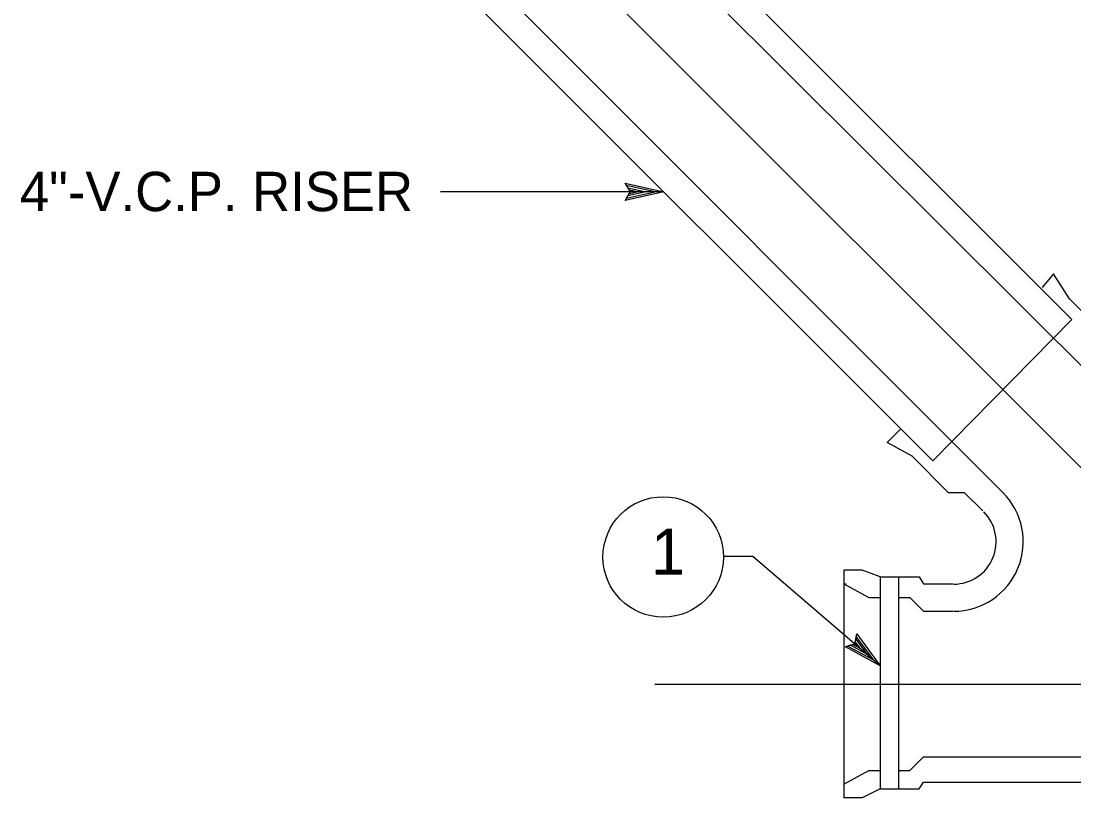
# Model space of a CAD drawing. Extents: x -119017 to -116080, y -104449 to -102845.
# Drawn here: x -116559.2 to -116398.8, y -103492.8 to -103374.5 of the extents above; entities that cross this region are included whole.
import ezdxf

# ---------------------------------------------------------------- set-up
doc = ezdxf.new("R2010")
doc.units = 0
for name, color, linetype in [('G-MARK', 7, 'Continuous'), ('G-TEXT', 7, 'Continuous'), ('Misc CnstDet(22)', 7, 'Continuous')]:
    doc.layers.add(name, color=color, linetype=linetype)

msp = doc.modelspace()

# ---------------------------------------------------------------- linework, layer by layer
at = {"layer": 'G-MARK'}
msp.add_line((-116461.26, -103400.51), (-116495.28, -103400.51), dxfattribs=at)
msp.add_lwpolyline([(-116428.29, -103472.7), (-116447.73, -103456.04), (-116452.24, -103456.04)], dxfattribs=at)
msp.add_circle((-116461.36, -103456.12), 9.18, dxfattribs=at)
at = {"layer": 'G-TEXT'}
for points in [[(-116467.17, -103399.19), (-116461.26, -103400.51), (-116467.17, -103401.82), (-116466.96, -103401.47), (-116462.63, -103400.51), (-116466.96, -103399.54), (-116466.75, -103399.89), (-116463.98, -103400.51), (-116466.75, -103401.12), (-116466.54, -103400.77), (-116465.34, -103400.51), (-116466.54, -103400.24), (-116466.38, -103400.51), (-116467.17, -103401.82), (-116466.38, -103400.51)], [(-116431.89, -103467.84), (-116428.29, -103472.7), (-116433.61, -103469.83), (-116433.22, -103469.7), (-116429.33, -103471.81), (-116431.96, -103468.24), (-116432.03, -103468.64), (-116430.34, -103470.92), (-116432.84, -103469.58), (-116432.45, -103469.45), (-116431.37, -103470.03), (-116432.1, -103469.04), (-116432.16, -103469.36), (-116433.61, -103469.83), (-116432.16, -103469.36)]]:
    msp.add_lwpolyline(points, close=True, dxfattribs=at)
at = {"layer": 'Misc CnstDet(22)'}
for p, q in [((-116364.77, -103475.48), (-116518.53, -103321.72)), ((-116399.13, -103419.95), (-116483.48, -103335.6)), ((-116381.78, -103442.85), (-116487.29, -103337.69)), ((-116409.55, -103446.33), (-116502.57, -103353.3)), ((-116420.31, -103441.47), (-116505, -103356.78)), ((-116420.31, -103441.47), (-116399.13, -103419.95)), ((-116412.67, -103449.1), (-116415.45, -103446.33)), ((-116433.84, -103458.13), (-116433.84, -103492.84)), ((-116431.07, -103458.13), (-116433.84, -103458.13)), ((-116428.29, -103459.17), (-116431.07, -103458.13)), ((-116428.29, -103459.17), (-116428.29, -103491.45)), ((-116428.29, -103459.17), (-116422.39, -103459.17)), ((-116425.51, -103459.17), (-116425.51, -103491.45)), ((-116422.39, -103459.17), (-116421.69, -103460.21)), ((-116433.84, -103460.21), (-116433.49, -103460.21)), ((-116433.84, -103460.21), (-116430.02, -103462.29)), ((-116421.69, -103460.21), (-116417.18, -103460.21)), ((-116430.02, -103462.29), (-116428.29, -103462.29)), ((-116425.51, -103462.29), (-116423.78, -103462.29)), ((-116423.78, -103462.29), (-116421.69, -103464.37)), ((-116421.69, -103464.37), (-116417.18, -103464.37)), ((-116462.65, -103475.48), (-116242.25, -103475.48)), ((-116423.78, -103488.67), (-116421.69, -103486.59)), ((-116421.69, -103486.59), (-116246.76, -103486.59)), ((-116433.84, -103490.75), (-116430.02, -103488.67)), ((-116430.02, -103488.67), (-116428.29, -103488.67)), ((-116425.51, -103488.67), (-116423.78, -103488.67)), ((-116428.29, -103491.45), (-116431.07, -103492.84)), ((-116428.29, -103491.45), (-116422.39, -103491.45)), ((-116422.39, -103491.45), (-116421.69, -103490.41)), ((-116421.69, -103490.41), (-116289.45, -103490.41)), ((-116431.07, -103492.84), (-116433.84, -103492.84))]:
    msp.add_line(p, q, dxfattribs=at)
for points in [[(-116393.93, -103424.81), (-116393.93, -103422.38), (-116399.48, -103416.82), (-116401.91, -103413), (-116403.64, -103415.09)], [(-116415.45, -103446.33), (-116417.88, -103446.33), (-116423.43, -103440.77), (-116427.25, -103438.69), (-116425.16, -103436.61)]]:
    msp.add_lwpolyline(points, dxfattribs=at)
for radius in [10.59, 6.46]:
    msp.add_arc((-116417.1, -103453.8), radius, 270, 45, dxfattribs=at)

# ---------------------------------------------------------------- texts
for s, height, p in [('4"-V.C.P. RISER', 6, (-116559.39, -103403.44)), ('1', 7, (-116463.23, -103458.82))]:
    msp.add_text(s, height=height, dxfattribs=at).set_placement(p)

doc.saveas('drawing.dxf')
